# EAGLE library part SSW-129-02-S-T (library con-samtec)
THROUGH-HOLE .025" SQ POST SOCKET Source: Samtec SSW.pdf
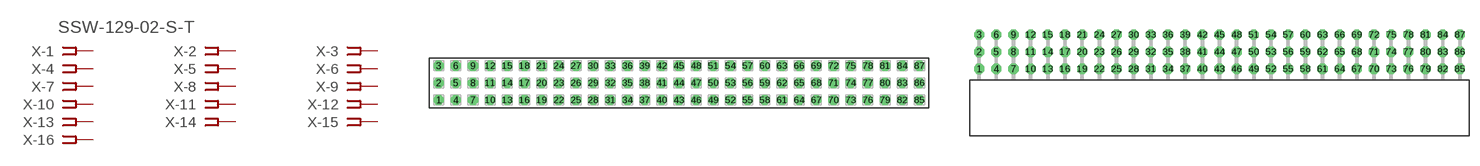
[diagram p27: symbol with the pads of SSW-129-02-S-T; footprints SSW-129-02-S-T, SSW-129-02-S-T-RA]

Designator prefix X; gates -1=FPINV -2=FPIN -3=FPIN -4=FPIN -5=FPIN -6=FPIN -7=FPIN -8=FPIN -9=FPIN -10=FPIN -11=FPIN -12=FPIN -13=FPIN -14=FPIN -15=FPIN -16=FPIN -17=FPIN -18=FPIN -19=FPIN -20=FPIN -21=FPIN -22=FPIN -23=FPIN -24=FPIN -25=FPIN -26=FPIN -27=FPIN -28=FPIN -29=FPIN -30=FPIN -31=FPIN -32=FPIN -33=FPIN -34=FPIN -35=FPIN -36=FPIN -37=FPIN -38=FPIN -39=FPIN -40=FPIN -41=FPIN -42=FPIN -43=FPIN -44=FPIN -45=FPIN -46=FPIN -47=FPIN -48=FPIN -49=FPIN -50=FPIN -51=FPIN -52=FPIN -53=FPIN -54=FPIN -55=FPIN -56=FPIN -57=FPIN -58=FPIN -59=FPIN -60=FPIN -61=FPIN -62=FPIN -63=FPIN -64=FPIN -65=FPIN -66=FPIN -67=FPIN -68=FPIN -69=FPIN -70=FPIN -71=FPIN -72=FPIN -73=FPIN -74=FPIN -75=FPIN -76=FPIN -77=FPIN -78=FPIN -79=FPIN -80=FPIN -81=FPIN -82=FPIN -83=FPIN -84=FPIN -85=FPIN -86=FPIN -87=FPIN

## SSW-129-02-S-T (MPN: SSW-129-02-S-T; OC_FARNELL: unknown; OC_NEWARK: 82P9923)  [SSW-129-02-S-T]
1  -1:1  pas
2  -2:1  pas
3  -3:1  pas
4  -4:1  pas
5  -5:1  pas
6  -6:1  pas
7  -7:1  pas
8  -8:1  pas
9  -9:1  pas
10  -10:1  pas
11  -11:1  pas
12  -12:1  pas
13  -13:1  pas
14  -14:1  pas
15  -15:1  pas
16  -16:1  pas
17  -17:1  pas
18  -18:1  pas
19  -19:1  pas
20  -20:1  pas
21  -21:1  pas
22  -22:1  pas
23  -23:1  pas
24  -24:1  pas
25  -25:1  pas
26  -26:1  pas
27  -27:1  pas
28  -28:1  pas
29  -29:1  pas
30  -30:1  pas
31  -31:1  pas
32  -32:1  pas
33  -33:1  pas
34  -34:1  pas
35  -35:1  pas
36  -36:1  pas
37  -37:1  pas
38  -38:1  pas
39  -39:1  pas
40  -40:1  pas
41  -41:1  pas
42  -42:1  pas
43  -43:1  pas
44  -44:1  pas
45  -45:1  pas
46  -46:1  pas
47  -47:1  pas
48  -48:1  pas
49  -49:1  pas
50  -50:1  pas
51  -51:1  pas
52  -52:1  pas
53  -53:1  pas
54  -54:1  pas
55  -55:1  pas
56  -56:1  pas
57  -57:1  pas
58  -58:1  pas
59  -59:1  pas
60  -60:1  pas
61  -61:1  pas
62  -62:1  pas
63  -63:1  pas
64  -64:1  pas
65  -65:1  pas
66  -66:1  pas
67  -67:1  pas
68  -68:1  pas
69  -69:1  pas
70  -70:1  pas
71  -71:1  pas
72  -72:1  pas
73  -73:1  pas
74  -74:1  pas
75  -75:1  pas
76  -76:1  pas
77  -77:1  pas
78  -78:1  pas
79  -79:1  pas
80  -80:1  pas
81  -81:1  pas
82  -82:1  pas
83  -83:1  pas
84  -84:1  pas
85  -85:1  pas
86  -86:1  pas
87  -87:1  pas

## SSW-129-02-S-TRA (OC_FARNELL: unknown; OC_NEWARK: unknown)  [SSW-129-02-S-T-RA]
Pads as for SSW-129-02-S-T

## Footprint SSW-129-02-S-T (pad centres in mm)
THROUGH-HOLE .025" SQ POST SOCKET Source: Samtec SSW.pdf
drill 1 pad 1.5 octagon: 1 -35.56,-2.54; 2 -35.56,0; 3 -35.56,2.54; 4 -33.02,-2.54; 5 -33.02,0; 6 -33.02,2.54; 7 -30.48,-2.54; 8 -30.48,0; 9 -30.48,2.54; 10 -27.94,-2.54; 11 -27.94,0; 12 -27.94,2.54; 13 -25.4,-2.54; 14 -25.4,0; 15 -25.4,2.54; 16 -22.86,-2.54; 17 -22.86,0; 18 -22.86,2.54; 19 -20.32,-2.54; 20 -20.32,0; 21 -20.32,2.54; 22 -17.78,-2.54; 23 -17.78,0; 24 -17.78,2.54; 25 -15.24,-2.54; 26 -15.24,0; 27 -15.24,2.54; 28 -12.7,-2.54; 29 -12.7,0; 30 -12.7,2.54; 31 -10.16,-2.54; 32 -10.16,0; 33 -10.16,2.54; 34 -7.62,-2.54; 35 -7.62,0; 36 -7.62,2.54; 37 -5.08,-2.54; 38 -5.08,0; 39 -5.08,2.54; 40 -2.54,-2.54; 41 -2.54,0; 42 -2.54,2.54; 43 0,-2.54; 44 0,0; 45 0,2.54; 46 2.54,-2.54; 47 2.54,0; 48 2.54,2.54; 49 5.08,-2.54; 50 5.08,0; 51 5.08,2.54; 52 7.62,-2.54; 53 7.62,0; 54 7.62,2.54; 55 10.16,-2.54; 56 10.16,0; 57 10.16,2.54; 58 12.7,-2.54; 59 12.7,0; 60 12.7,2.54; 61 15.24,-2.54; 62 15.24,0; 63 15.24,2.54; 64 17.78,-2.54; 65 17.78,0; 66 17.78,2.54; 67 20.32,-2.54; 68 20.32,0; 69 20.32,2.54; 70 22.86,-2.54; 71 22.86,0; 72 22.86,2.54; 73 25.4,-2.54; 74 25.4,0; 75 25.4,2.54; 76 27.94,-2.54; 77 27.94,0; 78 27.94,2.54; 79 30.48,-2.54; 80 30.48,0; 81 30.48,2.54; 82 33.02,-2.54; 83 33.02,0; 84 33.02,2.54; 85 35.56,-2.54; 86 35.56,0; 87 35.56,2.54

## Footprint SSW-129-02-S-T-RA (pad centres in mm)
THROUGH-HOLE .025" SQ POST SOCKET Source: Samtec SSW.pdf
drill 1 pad 1.5 octagon: 1 -35.56,1.524; 2 -35.56,4.064; 3 -35.56,6.604; 4 -33.02,1.524; 5 -33.02,4.064; 6 -33.02,6.604; 7 -30.48,1.524; 8 -30.48,4.064; 9 -30.48,6.604; 10 -27.94,1.524; 11 -27.94,4.064; 12 -27.94,6.604; 13 -25.4,1.524; 14 -25.4,4.064; 15 -25.4,6.604; 16 -22.86,1.524; 17 -22.86,4.064; 18 -22.86,6.604; 19 -20.32,1.524; 20 -20.32,4.064; 21 -20.32,6.604; 22 -17.78,1.524; 23 -17.78,4.064; 24 -17.78,6.604; 25 -15.24,1.524; 26 -15.24,4.064; 27 -15.24,6.604; 28 -12.7,1.524; 29 -12.7,4.064; 30 -12.7,6.604; 31 -10.16,1.524; 32 -10.16,4.064; 33 -10.16,6.604; 34 -7.62,1.524; 35 -7.62,4.064; 36 -7.62,6.604; 37 -5.08,1.524; 38 -5.08,4.064; 39 -5.08,6.604; 40 -2.54,1.524; 41 -2.54,4.064; 42 -2.54,6.604; 43 0,1.524; 44 0,4.064; 45 0,6.604; 46 2.54,1.524; 47 2.54,4.064; 48 2.54,6.604; 49 5.08,1.524; 50 5.08,4.064; 51 5.08,6.604; 52 7.62,1.524; 53 7.62,4.064; 54 7.62,6.604; 55 10.16,1.524; 56 10.16,4.064; 57 10.16,6.604; 58 12.7,1.524; 59 12.7,4.064; 60 12.7,6.604; 61 15.24,1.524; 62 15.24,4.064; 63 15.24,6.604; 64 17.78,1.524; 65 17.78,4.064; 66 17.78,6.604; 67 20.32,1.524; 68 20.32,4.064; 69 20.32,6.604; 70 22.86,1.524; 71 22.86,4.064; 72 22.86,6.604; 73 25.4,1.524; 74 25.4,4.064; 75 25.4,6.604; 76 27.94,1.524; 77 27.94,4.064; 78 27.94,6.604; 79 30.48,1.524; 80 30.48,4.064; 81 30.48,6.604; 82 33.02,1.524; 83 33.02,4.064; 84 33.02,6.604; 85 35.56,1.524; 86 35.56,4.064; 87 35.56,6.604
